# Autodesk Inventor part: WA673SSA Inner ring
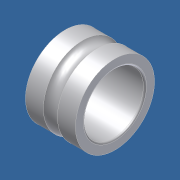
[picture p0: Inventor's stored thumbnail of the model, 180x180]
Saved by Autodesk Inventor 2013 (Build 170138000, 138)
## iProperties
Category: PARTsolutions
Created: 2011-07
Part Number: WA673SSA Inner ring
Catalog Web Link: www.cadenas.de
Description: Six types ir - Metric system sizes
Document SubType Name: Modeling
Designer: PARTsolutions
Density: 1 g/cm^3
Material: Générique
NB: WA673SSA Inner ring
NN: Six types ir
NT: Metric system sizes
NBSYN: $ORDER. Inner ring
LINA: WA673SSA Inner ring
SD: 3.0
D: 6
B: 2.0
R: 0.08
ORDER: WA673SSA
CR: 242
COR: 94
CRF: 25
CORF: 9,5
LSG: 60 000
LSO: 71 000
MASS: 0.20
D1: 7.2
D2: 7.2
C1: 0.6
C2: 0.6
ORDER1: 673
WSS: WA673SSA
WDS: SSA
UTWF: FL673
FORSS: FLWA673SA
FORDS: SSA
DA1: 3,6
DA2: 4,1
DA: 5,4
RAS: 0,08
MASS1: 0.26
B1: 2.5
VERS: 3
X: 1.500
N: 9
O: 14.130
RB: 0.444
KT: DUMMY
SUPPLIER: NTN
ARTICLENO: WA673SSA Inner ring
BOMINFO: WA673SSA Inner ring
CREATOR: CADENAS GmbH
PSOL_IDENT_0: {\\10.0.0.251\ps_data\23d-libs\ntn\ball_roller_bearings\miniature_extra_small_bb\metric_system_sizes
PSOL_IDENT_1: \mss_ir.prj},189 {VTYP=3D},{NB=WA673SSA Inner ring},{LINA=WA673SSA Inner ring},{NN=Six types ir},{DA
PSOL_IDENT_2: TE=11.12.2007 08:48:23},{GEOMDATE=28.06.2007 12:57:00},{VERSION=},{LINEID=12590},{LINESUBID=-1},{WBV
PSOL_IDENT_3: AR=}  {NB=WA673SSA Inner ring},{LINA=WA673SSA Inner ring},{KT=DUMMY},{IDNR=},{SD=3.0},{D=6},{B=2.0},
PSOL_IDENT_4: {R=0.08},{ORDER=WA673SSA},{CR=242},{COR=94},{CRF=25},{CORF=9,5},{LSG=60 000},{LSO=71 000},{MASS=0.20
PSOL_IDENT_5: },{D1=7.2},{D2=7.2},{C1=0.6},{C2=0.6},{ORDER1=673},{WSS=WA673SSA},{WDS=SSA},{UTWF=FL673},{FORSS=FLWA
PSOL_IDENT_6: 673SA},{FORDS=SSA},{DA1=3,6},{DA2=4,1},{DA=5,4},{RAS=0,08},{MASS1=0.26},{B1=2.5},{VERS=3},{X=1.5},{N
PSOL_IDENT_7: =9},{O=14.13},{RB=0.444}
Title: WA673SSA Inner ring
Author: Cadenas PARTsolutions
Comments: Metric system sizes
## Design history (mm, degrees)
sketch "Sketch_2"
  geometry: L1 (2.5, 0)-(0, 0); L2 (0, 1.98)-(0, 1.58); L3 (0.08, 1.5)-(2.42, 1.5); L4 (2.5, 1.58)-(2.5, 1.98); L5 (2.5, 1.98)-(1.602, 1.98); L6 (0.898, 1.98)-(0, 1.98); A1 r 0.08 centre (0.08, 1.58) between (0, 1.58) and (0.08, 1.5); A2 r 0.08 centre (2.42, 1.58) between (2.42, 1.5) and (2.5, 1.58); A3 r 0.444 centre (1.25, 2.25) between (0.898, 1.98) and (1.602, 1.98)
  constraints: 12 end point, 6 point on circle, 3 centre point
revolve "Revolution1" sketch "Sketch_2" stored, may be unused: angle "d0" = 360 deg
node "mss_ir_XY"
node "mss_ir_YZ"
node "mss_ir_ZX"
node "mss_ir_X"
node "mss_ir_Y"
node "mss_ir_Z"
node "mss_ir_Center"
node "Solide1"
node "Corps solides"
node "Corps surfaciques"
